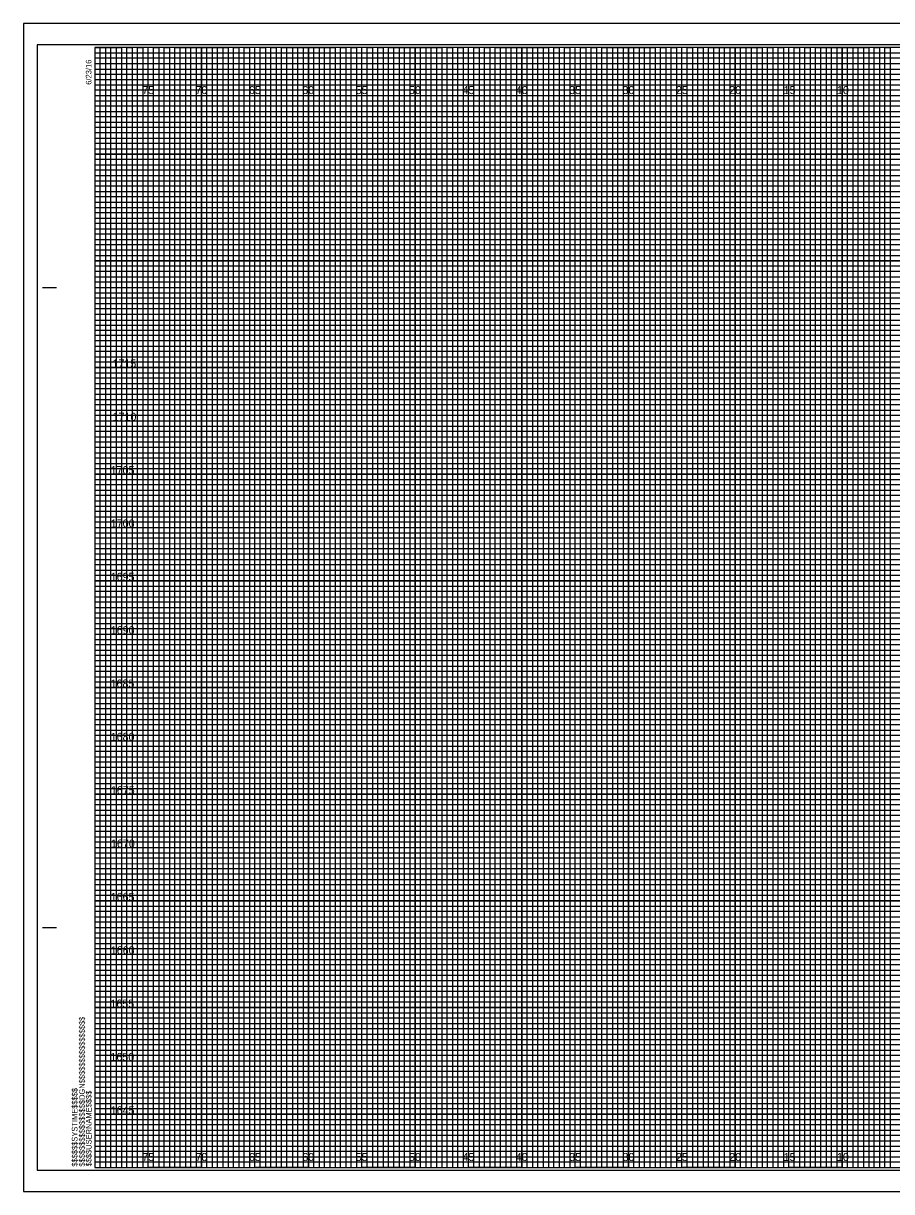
# Model space of a CAD drawing. Extents: x -407 to -239, y -3 to 766.
# Drawn here: x -407 to -325.7, y 106.6 to 216.1 of the extents above; entities that cross this region are included whole.
import ezdxf

# ---------------------------------------------------------------- set-up
doc = ezdxf.new("R2010")
doc.units = 0
for name, color, linetype in [('Raster_Level_0', 7, 'Continuous'), ('Scratch_Level_3', 7, 'Continuous'), ('Sheet Cross Section CELL', 7, 'Continuous'), ('Sheet Cross Section Grid Major CELL', 7, 'Continuous'), ('Sheet Cross Section Grid Middle CELL', 7, 'Continuous'), ('Sheet Cross Section Grid Minor 1 CELL', 7, 'Continuous'), ('Sheet Cross Section Grid Minor 2 CELL', 7, 'Continuous'), ('Sheet Cutting Line CELL', 7, 'Continuous'), ('Sheet DOT Grid CELL', 7, 'Continuous'), ('Sheet Plot Border Inside CELL', 7, 'Continuous'), ('Sheet Plot Border Outside CELL', 7, 'Continuous')]:
    doc.layers.add(name, color=color, linetype=linetype)

msp = doc.modelspace()

# ---------------------------------------------------------------- linework, layer by layer
at = {"layer": 'Sheet Cross Section CELL'}
for p, q in [((-405.22, 191.38), (-403.97, 191.38)), ((-405.17, 191.38), (-403.92, 191.38)), ((-405.22, 131.38), (-403.97, 131.38)), ((-405.17, 131.38), (-403.92, 131.38)), ((-400.32, 108.88), (-400.32, 108.88)), ((-400.32, 108.88), (-400.32, 108.88)), ((-400.32, 108.88), (-400.32, 108.88)), ((-400.32, 108.88), (-400.32, 108.88)), ((-400.32, 108.88), (-400.32, 108.88)), ((-400.32, 108.88), (-400.32, 108.88)), ((-400.32, 108.88), (-400.32, 108.88))]:
    msp.add_line(p, q, dxfattribs=at)
msp.add_lwpolyline([(-240.32, 213.88), (-400.32, 213.88), (-400.32, 108.88), (-240.32, 108.88)], close=True, dxfattribs=at)
at = {"layer": 'Sheet Cross Section Grid Major CELL'}
for p, q in [((-395.32, 213.88), (-400.32, 213.88)), ((-395.32, 108.88), (-395.32, 213.88)), ((-385.32, 213.88), (-390.32, 213.88)), ((-390.32, 213.88), (-390.32, 108.88)), ((-385.32, 108.88), (-385.32, 213.88)), ((-375.32, 213.88), (-380.32, 213.88)), ((-380.32, 213.88), (-380.32, 108.88)), ((-375.32, 108.88), (-375.32, 213.88)), ((-365.32, 213.88), (-370.32, 213.88)), ((-370.32, 213.88), (-370.32, 108.88)), ((-365.32, 108.88), (-365.32, 213.88)), ((-355.32, 213.88), (-360.32, 213.88)), ((-360.32, 213.88), (-360.32, 108.88)), ((-355.32, 108.88), (-355.32, 213.88)), ((-345.32, 213.88), (-350.32, 213.88)), ((-350.32, 213.88), (-350.32, 108.88)), ((-345.32, 108.88), (-345.32, 213.88)), ((-335.32, 213.88), (-340.32, 213.88)), ((-340.32, 213.88), (-340.32, 108.88)), ((-335.32, 108.88), (-335.32, 213.88)), ((-325.32, 213.88), (-330.32, 213.88)), ((-330.32, 213.88), (-330.32, 108.88)), ((-390.32, 108.88), (-395.32, 108.88)), ((-380.32, 108.88), (-385.32, 108.88)), ((-370.32, 108.88), (-375.32, 108.88)), ((-360.32, 108.88), (-365.32, 108.88)), ((-350.32, 108.88), (-355.32, 108.88)), ((-340.32, 108.88), (-345.32, 108.88)), ((-330.32, 108.88), (-335.32, 108.88))]:
    msp.add_line(p, q, dxfattribs=at)
for points in [[(-400.32, 208.88), (-240.32, 208.88), (-240.32, 203.88), (-400.32, 203.88)], [(-400.32, 198.88), (-240.32, 198.88), (-240.32, 193.88), (-400.32, 193.88)], [(-400.32, 188.88), (-240.32, 188.88), (-240.32, 183.88), (-400.32, 183.88)], [(-400.32, 178.88), (-240.32, 178.88), (-240.32, 173.88), (-400.32, 173.88)], [(-400.32, 168.88), (-240.32, 168.88), (-240.32, 163.88), (-400.32, 163.88)], [(-400.32, 158.88), (-240.32, 158.88), (-240.32, 153.88), (-400.32, 153.88)], [(-400.32, 148.88), (-240.32, 148.88), (-240.32, 143.88), (-400.32, 143.88)], [(-400.32, 138.88), (-240.32, 138.88), (-240.32, 133.88), (-400.32, 133.88)], [(-400.32, 128.88), (-240.32, 128.88), (-240.32, 123.88), (-400.32, 123.88)], [(-400.32, 118.88), (-240.32, 118.88), (-240.32, 113.88), (-400.32, 113.88)]]:
    msp.add_lwpolyline(points, dxfattribs=at)
at = {"layer": 'Sheet Cross Section Grid Middle CELL'}
for points in [[(-400.32, 213.88), (-397.82, 213.88), (-397.82, 108.88), (-392.82, 108.88), (-392.82, 213.88), (-387.82, 213.88), (-387.82, 108.88), (-382.82, 108.88), (-382.82, 213.88), (-377.82, 213.88), (-377.82, 108.88), (-372.82, 108.88), (-372.82, 213.88), (-367.82, 213.88), (-367.82, 108.88), (-362.82, 108.88), (-362.82, 213.88), (-357.82, 213.88), (-357.82, 108.88), (-352.82, 108.88), (-352.82, 213.88), (-347.82, 213.88), (-347.82, 108.88), (-342.82, 108.88), (-342.82, 213.88), (-337.82, 213.88), (-337.82, 108.88), (-332.82, 108.88), (-332.82, 213.88), (-327.82, 213.88), (-327.82, 108.88), (-322.82, 108.88)], [(-400.32, 211.38), (-262.82, 211.38)], [(-400.32, 201.38), (-240.32, 201.38), (-240.32, 206.38), (-400.32, 206.38)], [(-400.32, 191.38), (-240.32, 191.38), (-240.32, 196.38), (-400.32, 196.38)], [(-400.32, 181.38), (-240.32, 181.38), (-240.32, 186.38), (-400.32, 186.38)], [(-400.32, 171.38), (-240.32, 171.38), (-240.32, 176.38), (-400.32, 176.38)], [(-400.32, 161.38), (-240.32, 161.38), (-240.32, 166.38), (-400.32, 166.38)], [(-400.32, 151.38), (-240.32, 151.38), (-240.32, 156.38), (-400.32, 156.38)], [(-400.32, 141.38), (-240.32, 141.38), (-240.32, 146.38), (-400.32, 146.38)], [(-400.32, 131.38), (-240.32, 131.38), (-240.32, 136.38), (-400.32, 136.38)], [(-400.32, 121.38), (-240.32, 121.38), (-240.32, 126.38), (-400.32, 126.38)], [(-400.32, 111.38), (-240.32, 111.38), (-240.32, 116.38), (-400.32, 116.38)]]:
    msp.add_lwpolyline(points, dxfattribs=at)
at = {"layer": 'Sheet Cross Section Grid Minor 1 CELL'}
for p, q in [((-400.32, 213.38), (-270.32, 213.38)), ((-270.32, 212.87), (-400.32, 212.87)), ((-400.32, 212.87), (-400.32, 212.38)), ((-400.32, 212.38), (-270.32, 212.38)), ((-270.32, 211.82), (-400.32, 211.82)), ((-400.32, 211.82), (-400.32, 210.88)), ((-400.32, 210.88), (-240.32, 210.88))]:
    msp.add_line(p, q, dxfattribs=at)
for points in [[(-400.32, 210.38), (-265.32, 210.38), (-240.32, 210.38), (-240.32, 209.88), (-400.32, 209.88)], [(-400.32, 209.38), (-240.32, 209.38), (-240.32, 208.38), (-400.32, 208.38)], [(-400.32, 207.88), (-240.32, 207.88), (-240.32, 207.38), (-400.32, 207.37)], [(-400.32, 206.88), (-240.32, 206.88), (-240.32, 205.88), (-400.32, 205.88)], [(-400.32, 205.38), (-240.32, 205.38), (-240.32, 204.88), (-400.32, 204.88)], [(-400.32, 204.38), (-240.32, 204.38), (-240.32, 203.38), (-400.32, 203.38)], [(-400.32, 202.88), (-240.32, 202.88), (-240.32, 202.38), (-400.32, 202.38)], [(-400.32, 201.88), (-240.32, 201.88), (-240.32, 200.88), (-400.32, 200.88)], [(-400.32, 200.38), (-240.32, 200.38), (-240.32, 199.88), (-400.32, 199.88)], [(-400.32, 199.38), (-240.32, 199.38), (-240.32, 198.38), (-400.32, 198.38)], [(-400.32, 197.88), (-240.32, 197.88), (-240.32, 197.38), (-400.32, 197.38)], [(-400.32, 196.88), (-240.32, 196.88), (-240.32, 195.85), (-240.32, 195.38), (-240.32, 194.88), (-400.32, 194.88)], [(-400.32, 195.88), (-240.32, 195.88), (-240.32, 195.38), (-400.32, 195.38)], [(-400.32, 194.38), (-240.32, 194.38), (-240.32, 193.38), (-400.32, 193.39)], [(-400.32, 193.39), (-240.32, 193.38), (-240.32, 192.88), (-400.32, 192.88)], [(-400.32, 192.38), (-240.32, 192.38), (-240.32, 191.88), (-400.32, 191.88)], [(-400.32, 190.88), (-240.32, 190.88), (-240.32, 190.38), (-400.32, 190.38)], [(-400.32, 189.88), (-240.32, 189.88), (-240.32, 189.38), (-400.32, 189.38)], [(-400.35, 188.32), (-240.32, 188.32), (-240.32, 187.82), (-400.35, 187.82)], [(-400.32, 187.38), (-240.32, 187.38), (-240.32, 186.88), (-400.32, 186.88)], [(-400.32, 185.88), (-240.32, 185.88), (-240.32, 185.38), (-400.32, 185.38)], [(-400.32, 184.88), (-240.32, 184.88), (-240.32, 184.38), (-400.32, 184.38)], [(-400.32, 183.38), (-240.32, 183.38), (-240.32, 182.88), (-400.32, 182.88)], [(-400.32, 182.38), (-240.32, 182.38), (-240.32, 181.88), (-400.32, 181.88)], [(-400.32, 180.88), (-240.32, 180.88), (-240.32, 180.38), (-400.32, 180.38)], [(-400.32, 179.88), (-240.32, 179.88), (-240.32, 179.38), (-400.32, 179.38)], [(-400.32, 178.38), (-240.32, 178.38), (-240.32, 177.87), (-400.32, 177.88)], [(-400.32, 177.38), (-240.32, 177.38), (-240.32, 176.88), (-400.32, 176.88)], [(-400.32, 175.88), (-240.32, 175.88), (-240.32, 175.38), (-400.32, 175.38)], [(-400.32, 174.88), (-240.32, 174.88), (-240.32, 174.38), (-400.32, 174.38)], [(-400.32, 173.38), (-240.32, 173.38), (-240.32, 172.88), (-400.32, 172.88)], [(-400.32, 172.38), (-240.32, 172.38), (-240.32, 171.88), (-400.32, 171.88)], [(-400.32, 170.88), (-240.32, 170.88), (-240.32, 170.38), (-400.32, 170.38)], [(-400.32, 169.88), (-240.32, 169.88), (-240.32, 169.38), (-400.32, 169.38)], [(-400.32, 168.38), (-240.32, 168.38), (-240.32, 167.88), (-400.32, 167.88)], [(-400.32, 167.37), (-240.28, 167.33), (-240.32, 166.88), (-400.32, 166.88)], [(-400.32, 165.88), (-240.32, 165.88), (-240.32, 165.38), (-400.32, 165.38)], [(-400.32, 164.88), (-240.32, 164.88), (-240.32, 164.38), (-400.32, 164.38)], [(-400.32, 163.38), (-240.32, 163.38), (-240.32, 162.88), (-400.32, 162.88)], [(-400.32, 162.38), (-240.32, 162.38), (-240.32, 161.88), (-400.32, 161.88)], [(-400.32, 160.88), (-240.32, 160.88), (-240.32, 160.38), (-400.32, 160.38)], [(-400.32, 159.88), (-240.32, 159.88), (-240.32, 159.38), (-400.32, 159.38)], [(-400.32, 158.38), (-240.32, 158.38), (-240.32, 157.88), (-400.32, 157.88)], [(-400.32, 157.38), (-240.32, 157.38), (-240.32, 156.88), (-400.32, 156.88)], [(-400.32, 155.88), (-240.32, 155.88), (-240.32, 155.38), (-400.32, 155.38)], [(-400.32, 154.88), (-240.32, 154.88), (-240.32, 154.38), (-400.32, 154.38)], [(-400.32, 153.38), (-240.32, 153.38), (-240.32, 152.88), (-400.32, 152.88)], [(-400.32, 152.38), (-240.32, 152.38), (-240.32, 151.88), (-400.32, 151.88)], [(-400.32, 150.88), (-240.32, 150.88), (-240.32, 150.38), (-400.32, 150.38)], [(-400.32, 149.88), (-240.32, 149.88), (-240.32, 149.38), (-400.32, 149.38)], [(-400.32, 148.38), (-240.32, 148.38), (-240.32, 147.87), (-400.32, 147.88)], [(-400.32, 147.38), (-240.32, 147.38), (-240.32, 146.88), (-400.32, 146.88)], [(-400.32, 145.88), (-240.32, 145.88), (-240.32, 145.38), (-400.32, 145.38)], [(-400.32, 144.88), (-240.32, 144.88), (-240.32, 144.38), (-400.32, 144.38)], [(-400.32, 143.38), (-240.32, 143.38), (-240.32, 142.88), (-400.32, 142.88)], [(-400.32, 142.38), (-240.32, 142.38), (-240.32, 141.88), (-400.32, 141.88)], [(-400.32, 140.88), (-240.32, 140.88), (-240.32, 140.38), (-400.32, 140.38)], [(-400.32, 139.88), (-240.32, 139.88), (-240.32, 139.38), (-400.32, 139.38)], [(-400.32, 138.38), (-240.32, 138.38), (-240.32, 137.88), (-400.32, 137.88)], [(-400.32, 137.37), (-240.28, 137.33), (-240.32, 136.88), (-400.32, 136.88)], [(-400.32, 135.88), (-240.32, 135.88), (-240.32, 135.38), (-400.32, 135.38)], [(-400.32, 134.88), (-240.32, 134.88), (-240.32, 134.38), (-400.32, 134.38)], [(-400.32, 133.38), (-240.32, 133.38), (-240.32, 132.88), (-400.32, 132.88)], [(-400.32, 132.38), (-240.32, 132.38), (-240.32, 131.88), (-400.32, 131.88)], [(-400.32, 130.88), (-240.32, 130.88), (-240.32, 130.38), (-400.32, 130.38)], [(-400.32, 129.88), (-240.32, 129.88), (-240.32, 129.38), (-400.32, 129.38)], [(-400.32, 128.38), (-240.32, 128.38), (-240.32, 127.88), (-400.32, 127.88)], [(-400.32, 127.38), (-240.32, 127.38), (-240.32, 126.88), (-400.32, 126.88)], [(-400.32, 125.88), (-240.32, 125.88), (-240.32, 125.38), (-400.32, 125.38)], [(-400.32, 124.88), (-240.32, 124.88), (-240.32, 124.38), (-400.32, 124.38)], [(-400.32, 123.38), (-240.32, 123.38), (-240.32, 122.88), (-400.32, 122.88)], [(-400.32, 122.38), (-240.32, 122.38), (-240.32, 121.88), (-400.32, 121.88)], [(-400.32, 120.88), (-240.32, 120.88), (-240.32, 120.38), (-400.32, 120.38)], [(-400.32, 119.88), (-240.32, 119.88), (-240.32, 119.38), (-400.32, 119.38)], [(-400.32, 118.38), (-240.32, 118.38), (-240.32, 117.88), (-400.32, 117.88)], [(-400.32, 117.38), (-240.32, 117.38), (-240.32, 116.88), (-400.32, 116.88)], [(-400.32, 115.88), (-240.32, 115.88), (-240.32, 115.38), (-400.32, 115.38)], [(-400.32, 114.88), (-240.32, 114.88), (-240.32, 114.38), (-400.32, 114.38)], [(-400.32, 113.38), (-240.32, 113.38), (-240.32, 112.88), (-400.32, 112.88)], [(-400.32, 112.38), (-240.32, 112.38), (-240.32, 111.88), (-400.32, 111.88)], [(-400.32, 110.88), (-240.32, 110.88), (-240.32, 110.38), (-400.32, 110.38)], [(-400.32, 109.88), (-240.32, 109.88), (-240.32, 109.38), (-400.32, 109.38)]]:
    msp.add_lwpolyline(points, dxfattribs=at)
at = {"layer": 'Sheet Cross Section Grid Minor 2 CELL'}
for points in [[(-400.32, 108.88), (-399.82, 108.88), (-399.82, 213.88), (-399.32, 213.88), (-399.32, 108.88)], [(-399.32, 108.88), (-398.82, 108.88), (-398.82, 213.88), (-398.32, 213.88), (-398.32, 108.88)], [(-397.82, 108.88), (-397.32, 108.88), (-397.32, 213.88), (-396.82, 213.88), (-396.82, 108.88)], [(-396.82, 108.88), (-396.32, 108.88), (-396.32, 213.88), (-395.82, 213.88), (-395.82, 108.88)], [(-395.32, 108.88), (-394.82, 108.88), (-394.82, 213.88), (-394.32, 213.88), (-394.32, 108.88)], [(-394.32, 108.88), (-393.82, 108.88), (-393.82, 213.88), (-393.32, 213.88), (-393.32, 108.88)], [(-392.82, 108.88), (-392.32, 108.88), (-392.32, 213.88), (-391.82, 213.88), (-391.82, 108.88)], [(-391.82, 108.88), (-391.32, 108.88), (-391.32, 213.88), (-390.82, 213.88), (-390.82, 108.88)], [(-390.32, 108.88), (-389.82, 108.88), (-389.82, 213.88), (-389.32, 213.88), (-389.32, 108.88)], [(-389.32, 108.88), (-388.82, 108.88), (-388.82, 213.88), (-388.32, 213.88), (-388.32, 108.88)], [(-387.82, 108.88), (-387.32, 108.88), (-387.32, 213.88), (-386.82, 213.88), (-386.82, 108.88)], [(-386.82, 108.88), (-386.32, 108.88), (-386.32, 213.88), (-385.82, 213.88), (-385.82, 108.88)], [(-385.32, 108.88), (-384.82, 108.88), (-384.82, 213.88), (-384.32, 213.88), (-384.32, 108.88)], [(-384.32, 108.88), (-383.82, 108.88), (-383.82, 213.88), (-383.32, 213.88), (-383.32, 108.88)], [(-382.82, 108.88), (-382.32, 108.88), (-382.32, 213.88), (-381.82, 213.88), (-381.82, 108.88)], [(-381.82, 108.88), (-381.32, 108.88), (-381.32, 213.88), (-380.82, 213.88), (-380.82, 108.88)], [(-380.32, 108.88), (-379.82, 108.88), (-379.82, 213.88), (-379.32, 213.88), (-379.32, 108.88)], [(-379.32, 108.88), (-378.82, 108.88), (-378.82, 213.88), (-378.32, 213.88), (-378.32, 108.88)], [(-377.82, 108.88), (-377.32, 108.88), (-377.32, 213.88), (-376.82, 213.88), (-376.82, 108.88)], [(-376.82, 108.88), (-376.32, 108.88), (-376.32, 213.88), (-375.82, 213.88), (-375.82, 108.88)], [(-375.32, 108.88), (-374.82, 108.88), (-374.82, 213.88), (-374.32, 213.88), (-374.32, 108.88)], [(-374.32, 108.88), (-373.82, 108.88), (-373.82, 213.88), (-373.32, 213.88), (-373.32, 108.88)], [(-372.82, 108.88), (-372.32, 108.88), (-372.32, 213.88), (-371.82, 213.88), (-371.82, 108.88)], [(-371.82, 108.88), (-371.32, 108.88), (-371.32, 213.88), (-370.82, 213.88), (-370.82, 108.88)], [(-370.32, 108.88), (-369.82, 108.88), (-369.82, 213.88), (-369.32, 213.88), (-369.32, 108.88)], [(-369.32, 108.88), (-368.82, 108.88), (-368.82, 213.88), (-368.32, 213.88), (-368.32, 108.88)], [(-367.82, 108.88), (-367.32, 108.88), (-367.32, 213.88), (-366.82, 213.88), (-366.82, 108.88)], [(-366.82, 108.88), (-366.32, 108.88), (-366.32, 213.88), (-365.82, 213.88), (-365.82, 108.88)], [(-365.32, 108.88), (-364.82, 108.88), (-364.82, 213.88), (-364.32, 213.88), (-364.32, 108.88)], [(-364.32, 108.88), (-363.82, 108.88), (-363.82, 213.88), (-363.32, 213.88), (-363.32, 108.88)], [(-362.82, 108.88), (-362.32, 108.88), (-362.32, 213.88), (-361.82, 213.88), (-361.82, 108.88)], [(-361.82, 108.88), (-361.32, 108.88), (-361.32, 213.88), (-360.82, 213.88), (-360.82, 108.88)], [(-360.32, 108.88), (-359.82, 108.88), (-359.82, 213.88), (-359.32, 213.88), (-359.32, 108.88)], [(-359.32, 108.88), (-358.82, 108.88), (-358.82, 213.88), (-358.32, 213.88), (-358.32, 108.88)], [(-357.82, 108.88), (-357.32, 108.88), (-357.32, 213.88), (-356.82, 213.88), (-356.82, 108.88)], [(-356.82, 108.88), (-356.32, 108.88), (-356.32, 213.88), (-355.82, 213.88), (-355.82, 108.88)], [(-355.32, 108.88), (-354.82, 108.88), (-354.82, 213.88), (-354.32, 213.88), (-354.32, 108.88)], [(-354.32, 108.88), (-353.82, 108.88), (-353.82, 213.88), (-353.32, 213.88), (-353.32, 108.88)], [(-352.82, 108.88), (-352.32, 108.88), (-352.32, 213.88), (-351.82, 213.88), (-351.82, 108.88)], [(-351.82, 108.88), (-351.32, 108.88), (-351.32, 213.88), (-350.82, 213.88), (-350.82, 108.88)], [(-350.32, 108.88), (-349.82, 108.88), (-349.82, 213.88), (-349.32, 213.88), (-349.32, 108.88)], [(-349.32, 108.88), (-348.82, 108.88), (-348.82, 213.88), (-348.32, 213.88), (-348.32, 108.88)], [(-347.82, 108.88), (-347.32, 108.88), (-347.32, 213.88), (-346.82, 213.88), (-346.82, 108.88)], [(-346.82, 108.88), (-346.32, 108.88), (-346.32, 213.88), (-345.82, 213.88), (-345.82, 108.88)], [(-345.32, 108.88), (-344.82, 108.88), (-344.82, 213.88), (-344.32, 213.88), (-344.32, 108.88)], [(-344.32, 108.88), (-343.82, 108.88), (-343.82, 213.88), (-343.32, 213.88), (-343.32, 108.88)], [(-342.82, 108.88), (-342.32, 108.88), (-342.32, 213.88), (-341.82, 213.88), (-341.82, 108.88)], [(-341.82, 108.88), (-341.32, 108.88), (-341.32, 213.88), (-340.82, 213.88), (-340.82, 108.88)], [(-340.32, 108.88), (-339.82, 108.88), (-339.82, 213.88), (-339.32, 213.88), (-339.32, 108.88)], [(-339.32, 108.88), (-338.82, 108.88), (-338.82, 213.88), (-338.32, 213.88), (-338.32, 108.88)], [(-337.82, 108.88), (-337.32, 108.88), (-337.32, 213.88), (-336.82, 213.88), (-336.82, 108.88)], [(-336.82, 108.88), (-336.32, 108.88), (-336.32, 213.88), (-335.82, 213.88), (-335.82, 108.88)], [(-335.32, 108.88), (-334.82, 108.88), (-334.82, 213.88), (-334.32, 213.88), (-334.32, 108.88)], [(-334.32, 108.88), (-333.82, 108.88), (-333.82, 213.88), (-333.32, 213.88), (-333.32, 108.88)], [(-332.82, 108.88), (-332.32, 108.88), (-332.32, 213.88), (-331.82, 213.88), (-331.82, 108.88)], [(-331.82, 108.88), (-331.32, 108.88), (-331.32, 213.88), (-330.82, 213.88), (-330.82, 108.88)], [(-330.32, 108.88), (-329.82, 108.88), (-329.82, 213.88), (-329.32, 213.88), (-329.32, 108.88)], [(-329.32, 108.88), (-328.82, 108.88), (-328.82, 213.88), (-328.32, 213.88), (-328.32, 108.88)], [(-327.82, 108.88), (-327.32, 108.88), (-327.32, 213.88), (-326.82, 213.88), (-326.82, 108.88)], [(-326.82, 108.88), (-326.32, 108.88), (-326.32, 213.88), (-325.82, 213.88), (-325.82, 108.88)]]:
    msp.add_lwpolyline(points, dxfattribs=at)
at = {"layer": 'Sheet Cutting Line CELL'}
for p, q in [((-238.67, 216.13), (-407.02, 216.13)), ((-407.02, 216.13), (-407.02, 106.63)), ((-407.02, 106.63), (-238.67, 106.63))]:
    msp.add_line(p, q, dxfattribs=at)
at = {"layer": 'Sheet DOT Grid CELL'}
for p, q in [((-395.32, 108.88), (-395.32, 213.88)), ((-390.32, 108.88), (-390.32, 213.88)), ((-385.32, 108.88), (-385.32, 213.88)), ((-380.32, 108.88), (-380.32, 213.88)), ((-375.32, 108.88), (-375.32, 213.88)), ((-370.32, 108.88), (-370.32, 213.88)), ((-365.32, 108.88), (-365.32, 213.88)), ((-360.32, 108.88), (-360.32, 213.88)), ((-355.32, 108.88), (-355.32, 213.88)), ((-350.32, 108.88), (-350.32, 213.88)), ((-345.32, 108.88), (-345.32, 213.88)), ((-340.32, 108.88), (-340.32, 213.88)), ((-335.32, 108.88), (-335.32, 213.88)), ((-330.32, 108.88), (-330.32, 213.88)), ((-400.32, 208.88), (-240.32, 208.88)), ((-400.32, 203.88), (-240.32, 203.88)), ((-400.32, 198.88), (-240.32, 198.88)), ((-400.32, 193.88), (-240.32, 193.88)), ((-400.32, 188.88), (-240.32, 188.88)), ((-400.32, 183.88), (-240.32, 183.88)), ((-400.32, 178.88), (-240.32, 178.88)), ((-400.32, 173.88), (-240.32, 173.88)), ((-400.32, 168.88), (-240.32, 168.88)), ((-400.32, 163.88), (-240.32, 163.88)), ((-400.32, 158.88), (-240.32, 158.88)), ((-400.32, 153.88), (-240.32, 153.88)), ((-400.32, 148.88), (-240.32, 148.88)), ((-400.32, 143.88), (-240.32, 143.88)), ((-400.32, 138.88), (-240.32, 138.88)), ((-400.32, 133.88), (-240.32, 133.88)), ((-400.32, 128.88), (-240.32, 128.88)), ((-400.32, 123.88), (-240.32, 123.88)), ((-400.32, 118.88), (-240.32, 118.88)), ((-400.32, 113.88), (-240.32, 113.88))]:
    msp.add_line(p, q, dxfattribs=at)
at = {"layer": 'Sheet Plot Border Inside CELL'}
msp.add_lwpolyline([(-405.72, 108.63), (-239.12, 108.63), (-239.12, 214.13), (-405.72, 214.13)], close=True, dxfattribs=at)
at = {"layer": 'Sheet Plot Border Outside CELL'}
msp.add_lwpolyline([(-407.02, 106.63), (-238.67, 106.63), (-238.67, 216.13), (-407.02, 216.13)], close=True, dxfattribs=at)

# ---------------------------------------------------------------- texts
at = {"layer": 'Raster_Level_0'}
for s, p in [('75', (-395.88, 209.5)), ('70', (-390.89, 209.5)), ('65', (-385.88, 209.5)), ('60', (-380.89, 209.5)), ('55', (-375.88, 209.5)), ('50', (-370.89, 209.5)), ('45', (-365.88, 209.5)), ('40', (-360.89, 209.5)), ('35', (-355.88, 209.5)), ('30', (-350.89, 209.5)), ('25', (-345.88, 209.5)), ('20', (-340.89, 209.5)), ('15', (-335.79, 209.5)), ('10', (-330.8, 209.5)), ('75', (-395.88, 109.5)), ('70', (-390.89, 109.5)), ('65', (-385.88, 109.5)), ('60', (-380.89, 109.5)), ('55', (-375.88, 109.5)), ('50', (-370.89, 109.5)), ('45', (-365.88, 109.5)), ('40', (-360.89, 109.5)), ('35', (-355.88, 109.5)), ('30', (-350.89, 109.5)), ('25', (-345.88, 109.5)), ('20', (-340.89, 109.5)), ('15', (-335.79, 109.5)), ('10', (-330.8, 109.5))]:
    msp.add_text(s, height=0.75, dxfattribs=at).set_placement(p)
at = {"layer": 'Scratch_Level_3'}
for s, p in [('1715', (-398.67, 183.88)), ('1710', (-398.66, 178.88)), ('1705', (-398.84, 173.88)), ('1700', (-398.83, 168.88)), ('1695', (-398.84, 163.88)), ('1690', (-398.83, 158.88)), ('1685', (-398.85, 153.88)), ('1680', (-398.84, 148.88)), ('1675', (-398.82, 143.88)), ('1670', (-398.81, 138.88)), ('1665', (-398.84, 133.88)), ('1660', (-398.83, 128.88)), ('1655', (-398.86, 123.88)), ('1650', (-398.86, 118.88)), ('1645', (-398.84, 113.88))]:
    msp.add_text(s, height=0.75, dxfattribs=at).set_placement(p)
at = {"layer": 'Sheet Cross Section CELL'}
for s, p in [('6/23/16', (-400.64, 210.38)), ('$$$$$$$$$$$$$$$$DGN$$$$$$$$$$$$$$$$', (-401.26, 108.97)), ('$$$$$$SYSTIME$$$$$', (-401.95, 108.97)), ('$$$$USERNAME$$$$', (-400.63, 108.99))]:
    msp.add_text(s, height=0.525, rotation=90, dxfattribs=at).set_placement(p)

doc.saveas('drawing.dxf')
